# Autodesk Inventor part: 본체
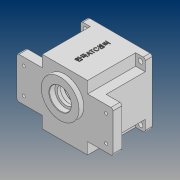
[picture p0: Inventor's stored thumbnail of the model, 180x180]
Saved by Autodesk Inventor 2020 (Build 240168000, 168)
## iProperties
Created: 2020-07
Part Number: 본체
Material: 일반
Document SubType Name: Modeling
Designer: PC312-02
Density: 1 g/cm^3
Appearance: 기본값
Author: PC312-02
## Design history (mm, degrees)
sketch "스케치1"
  geometry: L1 (33, -47)-(-33, -47); L2 (-33, 47)-(33, 47); L3 (-70, -30)-(-70, 30); L4 (70, 30)-(70, -30); L5 (-33, -47)-(-33, -30); L6 (-33, 30)-(-33, 47); L7 (33, 47)-(33, 30); L8 (33, -30)-(33, -47); L9 (-70, 30)-(-33, 30); L10 (33, 30)-(70, 30); L11 (70, -30)-(33, -30); L12 (-33, -30)-(-70, -30); 1 further point
  constraints: 24 end point, 10 parallel, 4 perpendicular, 3 horizontal
  dimensions: "d0" = 66 distance of L2.start L2.end; "d1" = 94 distance of L1.end L2.start; "d2" = 140 distance of L3.end L4.start; "d3" = 60 distance of L3.start L3.end; "d4" = 33 distance from line of L5 point (0, 0); "d5" = 33 distance from line of L8 point (0, 0); "d6" = 47 distance from line of point (0, 0) L1; "d7" = 47 distance from line of point (0, 0) L2; "d8" = 70 distance from line of point (0, 0) L4; "d9" = 140 distance between parallel lines of L3 L4; "d10" = 30 distance from line of point (0, 0) L11; "d11" = 60 distance between parallel lines of L10 L11
extrude "돌출1" new body sketch "스케치1" distance "d12" = 13; taper "d13" = 0 deg
sketch "스케치2"
  geometry: L1 (-33, 30)-(-33, 47) reference; L2 (33, -47)-(-33, -47); L3 (-33, 47)-(33, 47); L4 (-70, 30)-(-33, 30) reference; L5 (-47, -30)-(-47, 30); L6 (47, 30)-(47, -30); L7 (-47, 30)-(-33, 30); L8 (33, 30)-(47, 30); L9 (-33, -47)-(-33, -30); L10 (-33, 30)-(-33, 47); L11 (33, 47)-(33, 30); L12 (33, -30)-(33, -47); L13 (47, -30)-(33, -30); L14 (-33, -30)-(-47, -30); 1 further point
  constraints: 24 end point, 10 parallel, 4 perpendicular, 3 horizontal, 1 point on line
  dimensions: "d14" = 94 distance between parallel lines of L2 L3; "d16" = 94 distance between parallel lines of L6 L5; "d17" = 47 distance from line of point (0, 0) L5; "d18" = 30 distance from line of point (0, 0) L8; "d19" = 60 distance between parallel lines of L13 L8; "d20" = 66 distance between parallel lines of L1 L11; "d21" = 66 distance between parallel lines of L9 L12; "d22" = 33 distance from line of point (0, 0) L12; "d23" = 30 distance from line of point (0, 0) L14
extrude "돌출2" join sketch "스케치2" distance "d24" = 57; taper "d25" = 0 deg
sketch "스케치3"
  geometry: L1 (47, -47)-(-47, -47); L2 (-47, -47)-(-47, 47); L3 (-47, 47)-(47, 47); L4 (47, 47)-(47, -47); L5 (47, -47)-(-47, 47); L6 (-47, -47)-(47, 47); 1 further point
  constraints: 12 end point, 2 midpoint, 2 parallel, 1 horizontal, 1 perpendicular
  dimensions: "d26" = 94 distance of L2.end L3.end; "d27" = 94 distance of L1.end L2.end
extrude "돌출3" join sketch "스케치3" distance "d28" = 10; taper "d29" = 0 deg
sketch "스케치4"
  geometry: C1 r 27.5 at (0, 11); 1 further point
  constraints: 1 centre point, 1 vertical alignment
  dimensions: "d30" = 55 diameter of C1; "d31" = 11 distance of point (0, 0) C1.centre
extrude "돌출4" join sketch "스케치4" distance "d32" = 7; taper "d33" = 0 deg
sketch "스케치5"
  geometry: L1 (38.5, 20)-(-16.5, 20) reference; L2 (11, 20)-(11, -3); L3 (27, 20)-(27, 11.7); L4 (27, 11.7)-(23.5, 11.7); L5 (23.5, 11.7)-(23.5, 7); L6 (23.5, 7)-(28.5, 7); L7 (28.5, 7)-(28.5, -3); L8 (28.5, -3)-(11, -3); L9 (27, 20)-(11, 20); L10 (-20, 7)-(-20, -3); L11 (-9, -3)-(-9, 4); L12 (-9, 4)-(-10.5, 4); L13 (-10.5, 4)-(-10.5, 7); L14 (-10.5, 7)-(-20, 7); L15 (-9, -3)-(-20, -3); 1 further point
  constraints: 28 end point, 7 horizontal, 7 vertical, 3 horizontal alignment, 1 midpoint, 1 point on line
  dimensions: "d34" = 32 diameter of L3 L2; "d35" = 25 diameter of L5 L2; "d36" = 35 diameter of L7 L2; "d37" = 8.3 distance between parallel lines of L4 L1; "d38" = 10 distance between parallel lines of L8 L6; "d39" = 23 distance between parallel lines of L8 L1; "d40" = 31 distance from line of L10.end L2; "d41" = 22 diameter of L11 L10; "d42" = 19 diameter of L13 L10; "d43" = 7 distance from line of L11.start L12; "d44" = 3 distance between parallel lines of L14 L12
revolve "회전1" stored, may be unused: angle "d45" = 90 deg
revolve "회전2" stored, may be unused: angle "d46" = 90 deg
sketch "스케치6"
  geometry: C1 r 43 at (0, 0); 1 further point
  constraints: 1 centre point, 1 coincident
  dimensions: "d47" = 86 diameter of C1
extrude "돌출5" cut sketch "스케치6" distance "d48" = 9; taper "d49" = 0 deg
sketch "스케치7"
  geometry: L1 (36, 4)-(39.799, 4); L2 (36, -4)-(39.799, -4); L3 (0, 40)-(0, 0); L4 (0, 0)-(0, -40); L5 (-36, 4)-(-39.799, 4); L6 (-36, -4)-(-39.799, -4); A1 r 4 centre (36, 0) between (36, 4) and (36, -4); A2 r 4 centre (-36, 0) between (-36, -4) and (-36, 4); A3 r 40 centre (0, 0) between (-39.799, -4) and (39.799, -4); A4 r 40 centre (0, 0) between (39.799, 4) and (-39.799, 4); A5 r 21 centre (0, 11) between (8.978, -7.984) and (-8.978, -7.984); A6 r 15 centre (0, -20) between (-8.978, -7.984) and (8.978, -7.984); 3 further points
  constraints: 14 point on circle, 12 end point, 6 centre point, 5 symmetric about line, 3 coincident, 2 horizontal, 2 tangent, 2 vertical, 1 horizontal alignment, 1 other
  dimensions: "d53" = 36 distance of point (0, 0) A1.centre; "d54" = 8 diameter of A1; "d56" = 40 radius of A3; "d57" = 40 radius of A4; "d58" = 42 diameter of A5; "d59" = 30 diameter of A6
extrude "돌출6" cut sketch "스케치7" distance "d60" = 62; taper "d61" = 0 deg
sketch "스케치8"
  geometry: C1 r 17.5 at (0, 11) reference; C2 r 11 at (0, -20) reference; A1 r 21 centre (0, 11) between (8.978, -7.984) and (-8.978, -7.984); A2 r 15 centre (0, -20) between (-8.978, -7.984) and (8.978, -7.984); 1 further point
  constraints: 4 point on circle, 2 centre point, 2 coincident
  dimensions: "d64" = 30 diameter of A2; "d65" = 42 diameter of A1
extrude "돌출7" cut sketch "스케치8" distance "d62" = 55; taper "d63" = 0 deg
sketch "스케치11"
  geometry: 2 further points
  dimensions: "d66" = 60 horizontal distance of point (0, 0) point (-60, 19); "d67" = 19 vertical distance of point (-60, 19) point (0, 0)
hole "구멍1" sketch "스케치11" at (-60, 19) diameter "d68" = 4.5; stored, may be unused: countersink angle "d72" = 90 deg, drill point angle "d74" = 0 deg; dims "d69" = 8, "d70" = 10, "d71" = 5, "d73" = 13
sketch "스케치12"
  geometry: A1 r 4 centre (-36, 0) between (-36, -4) and (-36, 4) reference; 2 further points
  constraints: 1 coincident
hole "구멍2" sketch "스케치12" at (-36, 0) diameter "d81" = 3.242; stored, may be unused: countersink angle "d85" = 90 deg, drill point angle "d87" = 118 deg; dims "d82" = 7, "d83" = 10, "d84" = 5, "d86" = 9
sketch "스케치13"
  geometry: C1 r 3.5 at (40, 40); 1 further point
  constraints: 1 centre point
  dimensions: "d88" = 7 diameter of C1; "d89" = 40 horizontal distance of C1.centre point (0, 0); "d90" = 40 horizontal distance of C1.centre point (0, 0)
extrude "돌출8" cut sketch "스케치13" extent not by distance; stored distance "d91" = 0; taper "d92" = 0 deg
fillet "모깎기1" dims "d99" = 3
fillet "모깎기2" dims "d100" = 3
chamfer "모따기1" distance "d101" = 1; stored, may be unused: second distance "d102" = 2, angle "d103" = 45 deg
chamfer "모따기2" distance "d104" = 0.8; stored, may be unused: second distance "d105" = 2, angle "d106" = 30 deg
fillet "모깎기3" dims "d107" = 3
node "작업 평면1"
sketch "스케치14"
  geometry: L1 (-11, 80)-(77, 80) reference; 2 further points
  constraints: 1 vertical alignment, 1 other
  dimensions: "d109" = 40 distance from line of L1 point (33, 40)
feature "엠보싱1" sketch "스케치14" dims "d0" = 66, "d1" = 94, "d2" = 140, "d3" = 60, "d4" = 33, "d5" = 33, "d6" = 47, "d7" = 47, "d8" = 70, "d9" = 140, "d10" = 30, "d11" = 60, "d110" = 0.5, "d111" = 0
chamfer "모따기3" distance "d112" = 1; stored, may be unused: second distance "d113" = 2, angle "d114" = 45 deg
node "솔리드1"
pattern_linear "직사각형 패턴1" dims "d77" = 38, "d80" = 120
mirror "미러1"
pattern_linear "직사각형 패턴2" dims "d95" = 80, "d98" = 80
feature "A9D066F2-1C7D-4E18-AEED-F7BC21143FA4" dims "d68" = 4.5, "d69" = 8, "d70" = 10, "d71" = 5, "d72" = 90 deg, "d73" = 13, "d74" = 0
